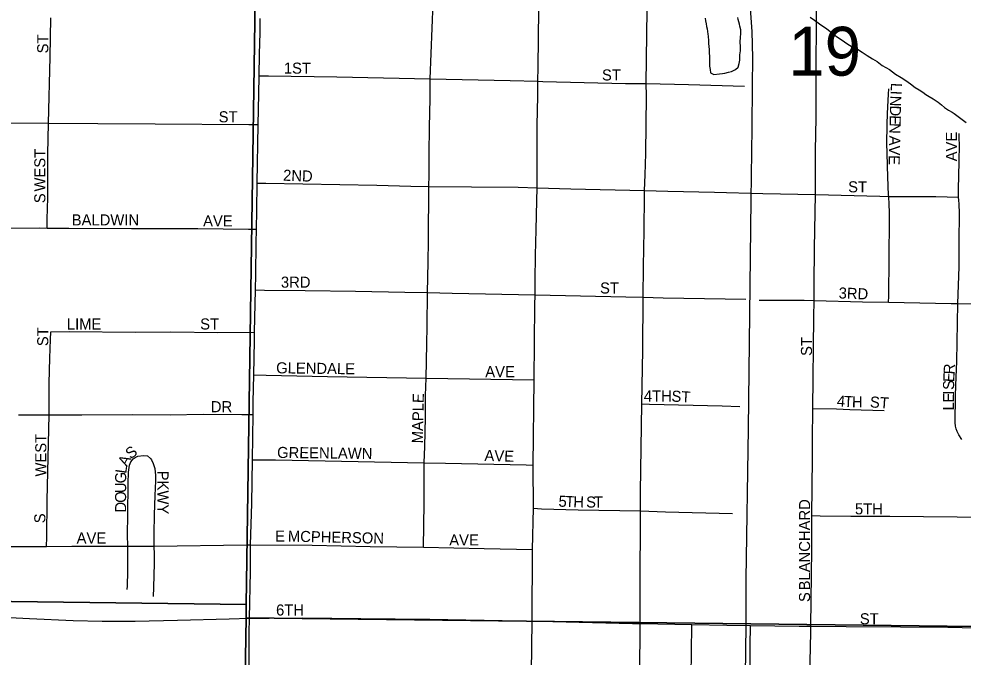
# Model space of a CAD drawing. Extents: x 1587405 to 1714697, y 1028970 to 1155083.
# Drawn here: x 1649935 to 1654205, y 1102813 to 1105700 of the extents above; entities that cross this region are included whole.
import ezdxf

# ---------------------------------------------------------------- set-up
doc = ezdxf.new("R2010")
doc.units = 0
for name, color, linetype in [('GM_X_City_Street', 7, 'Continuous'), ('GM_X_City_Street_Text', 7, 'Continuous'), ('GM_X_Minor_Lake', 7, 'Continuous'), ('GM_X_Minor_River', 7, 'Continuous'), ('GM_X_Rail_Line', 7, 'Continuous'), ('GM_X_Section', 7, 'Continuous'), ('GM_X_Section_Text', 7, 'Continuous')]:
    doc.layers.add(name, color=color, linetype=linetype)

msp = doc.modelspace()

# ---------------------------------------------------------------- linework, layer by layer
at = {"layer": 'GM_X_City_Street'}
for points in [[(1653536.6, 1104905.8), (1653536.7, 1104924.4), (1653537.6, 1105105), (1653539.7, 1105252.3), (1653540.3, 1105465.5), (1653542.3, 1105695.2), (1653545.1, 1105923.6), (1653546.9, 1106033.5), (1653546.5, 1106148.4), (1653547.5, 1106257.9)], [(1651794.9, 1105429.1), (1651808.8, 1105772.9), (1651811.8, 1105871.5), (1651812.3, 1105914.9)], [(1652281.6, 1105417.6), (1652282.3, 1105481.6), (1652286.5, 1105741.4), (1652288, 1105903)], [(1652771.8, 1105407), (1652777.5, 1105852.1), (1652777.5, 1105890.5)], [(1650068.7, 1105227.3), (1650075.5, 1105526.2), (1650078.8, 1105704.7)], [(1651021.5, 1105442.3), (1651023.3, 1105539.8), (1651025.1, 1105637.8), (1651025.5, 1105701.4)], [(1651017.3, 1105222.2), (1651019.9, 1105359.5), (1651021.5, 1105442.3)], [(1651021.5, 1105442.3), (1651063.7, 1105441.7), (1651372.8, 1105437.3), (1651794.9, 1105429.1)], [(1651788.5, 1104941.9), (1651790.4, 1104993), (1651790.3, 1105089.2), (1651791.9, 1105210.5), (1651794.3, 1105340), (1651794.9, 1105429.1)], [(1651794.9, 1105429.1), (1652156.5, 1105420.5), (1652281.6, 1105417.6)], [(1652278.7, 1104935.5), (1652278.9, 1105108.9), (1652277.7, 1105219.2), (1652280.8, 1105350.2), (1652281.6, 1105417.6)], [(1652281.6, 1105417.6), (1652303.9, 1105416.8), (1652678.4, 1105407.7), (1652771.8, 1105407)], [(1652764.3, 1104923.2), (1652766.6, 1104994.1), (1652769.6, 1105090.1), (1652772.6, 1105351.1), (1652771.8, 1105407)], [(1652771.8, 1105407), (1652962.5, 1105402.4), (1653215.7, 1105395.6)], [(1653868.2, 1104896.6), (1653867.8, 1104903.3), (1653866.3, 1104941.3), (1653862.9, 1105034), (1653860.7, 1105095.8), (1653860.1, 1105132.9), (1653861.3, 1105221.6), (1653862.9, 1105271.2), (1653866.1, 1105331.2), (1653867.7, 1105358.6), (1653868.8, 1105383.1)], [(1649688.8, 1105235.7), (1649733.6, 1105231.7), (1649896.9, 1105229.6), (1650068.7, 1105227.3)], [(1650062.2, 1104753.8), (1650062.9, 1104793.7), (1650064.7, 1104890.7), (1650065.6, 1105088.4), (1650068.7, 1105227.3)], [(1650068.7, 1105227.3), (1650291.3, 1105226.3), (1650550.4, 1105224.3), (1650973.8, 1105222.4), (1651017.3, 1105222.2)], [(1651012.2, 1104957), (1651017.3, 1105222.2)], [(1654184.5, 1104893.5), (1654184.6, 1104929.6), (1654186.4, 1105052.5), (1654187.7, 1105131.5), (1654187.3, 1105158.2), (1654186.8, 1105181.8)], [(1651008.8, 1104748.4), (1651009.9, 1104832.4), (1651012.2, 1104957)], [(1651012.2, 1104957), (1651050.9, 1104956.4), (1651552.7, 1104947.3), (1651707.6, 1104943.2), (1651788.5, 1104941.9)], [(1651782.5, 1104462.2), (1651785.2, 1104598.6), (1651786.9, 1104696.2), (1651788.5, 1104941.9)], [(1651788.5, 1104941.9), (1651981.2, 1104939.7), (1652192, 1104937.9), (1652278.7, 1104935.5)], [(1652269, 1104451.8), (1652269.8, 1104516.7), (1652271.1, 1104630.4), (1652274.6, 1104746.2), (1652277.3, 1104876), (1652278.7, 1104935.5)], [(1652278.7, 1104935.5), (1652430.8, 1104931.2), (1652764.3, 1104923.2)], [(1652758.2, 1104440.3), (1652758.9, 1104579.9), (1652762.2, 1104742), (1652763.3, 1104899.6), (1652764.3, 1104923.2)], [(1652764.3, 1104923.2), (1652869.4, 1104920.6), (1653080.9, 1104915.6), (1653298.7, 1104910.5), (1653536.6, 1104905.8)], [(1653531, 1104426.3), (1653531.8, 1104498), (1653532.7, 1104662.1), (1653536.6, 1104905.8)], [(1653536.6, 1104905.8), (1653827.6, 1104897.8), (1653868.2, 1104896.6)], [(1653868.1, 1104418.3), (1653869, 1104445.2), (1653870.4, 1104616.9), (1653872.2, 1104792.9), (1653871.9, 1104826.2), (1653871, 1104859.9), (1653868.2, 1104896.6)], [(1653868.2, 1104896.6), (1654080.9, 1104895.9), (1654184.5, 1104893.5)], [(1654181.5, 1104412.6), (1654186.5, 1104578.7), (1654187, 1104691.9), (1654188.7, 1104820.2), (1654186.8, 1104861.9), (1654185.5, 1104879.3), (1654184.5, 1104893.5)], [(1649680.4, 1104754.7), (1649866.1, 1104753.4), (1650026.6, 1104754), (1650062.2, 1104753.8)], [(1650062.2, 1104753.8), (1650160.4, 1104753.2), (1650443.8, 1104751.9), (1650744.1, 1104750.9), (1650972.6, 1104748.8), (1651008.8, 1104748.4)], [(1651003.9, 1104474.6), (1651005.6, 1104544.2), (1651008, 1104685.8), (1651008.8, 1104748.4)], [(1650999.5, 1104282), (1651003.9, 1104474.6)], [(1651003.9, 1104474.6), (1651045.6, 1104472.9), (1651228.7, 1104471.9), (1651456.8, 1104467.4), (1651679.6, 1104463), (1651782.5, 1104462.2)], [(1651776, 1104074.8), (1651780.1, 1104229.5), (1651781, 1104308.7), (1651782.5, 1104462.2)], [(1651782.5, 1104462.2), (1651894.2, 1104459.6), (1652269, 1104451.8)], [(1652264.9, 1104067.1), (1652268.5, 1104405.2), (1652269, 1104451.8)], [(1652269, 1104451.8), (1652678.7, 1104442.5), (1652758.2, 1104440.3)], [(1652751.6, 1103958.4), (1652756.8, 1104201.8), (1652758.2, 1104440.3)], [(1652758.2, 1104440.3), (1652848.9, 1104438.7), (1653222.4, 1104431.8)], [(1653282.5, 1104427.9), (1653329.8, 1104427), (1653485.4, 1104427.5), (1653531, 1104426.3)], [(1653525.4, 1103937.7), (1653530, 1104350.4), (1653531, 1104426.3)], [(1653531, 1104426.3), (1653750.5, 1104420.3), (1653868.1, 1104418.3)], [(1653868.1, 1104418.3), (1654151.5, 1104412.9), (1654181.5, 1104412.6)], [(1654198.4, 1103797.2), (1654186.1, 1103818.6), (1654178.2, 1103833.1), (1654173.7, 1103845.4), (1654170.9, 1103858.2), (1654169.5, 1103874.6), (1654170.8, 1103993.1), (1654171.9, 1104042.4), (1654176.4, 1104150.6), (1654181.5, 1104412.6)], [(1654181.5, 1104412.6), (1654505.2, 1104410.9)], [(1650070.8, 1103908.4), (1650072.1, 1104051.7), (1650073.9, 1104164.8), (1650077.3, 1104249.5), (1650078.7, 1104283.8)], [(1650078.7, 1104283.8), (1650163.2, 1104285), (1650459.9, 1104283.4), (1650622.4, 1104283.6), (1650833.7, 1104281.8), (1650999.5, 1104282)], [(1650997, 1104089.5), (1650999.7, 1104243.2), (1650999.5, 1104282)], [(1650993.9, 1103910.3), (1650994.7, 1103965.6), (1650997, 1104089.5)], [(1650997, 1104089.5), (1651053, 1104088.2), (1651330.3, 1104081.5), (1651776, 1104074.8)], [(1651768, 1103691.9), (1651769.9, 1103766.1), (1651773.5, 1103896), (1651774.1, 1103996.5), (1651776, 1104074.8)], [(1651776, 1104074.8), (1652264.9, 1104067.1)], [(1652260.6, 1103681.4), (1652264.9, 1104067.1)], [(1652745.4, 1103474.8), (1652746, 1103499.7), (1652745.5, 1103558.4), (1652751.6, 1103958.4)], [(1652751.6, 1103958.4), (1652785.8, 1103957.5), (1653115, 1103949.2), (1653195.7, 1103946.5)], [(1649933.1, 1103908.3), (1650030.9, 1103908.9), (1650070.8, 1103908.4)], [(1650070.8, 1103908.4), (1650219.1, 1103908.5), (1650446.3, 1103910.3), (1650618.7, 1103909.5), (1650767.2, 1103911.3), (1650943.2, 1103910.5), (1650993.9, 1103910.3)], [(1650990.7, 1103705.2), (1650993.9, 1103910.3)], [(1653521.2, 1103453.1), (1653523.7, 1103710.9), (1653523.5, 1103825.8), (1653524.5, 1103907.7), (1653525.4, 1103937.7)], [(1653525.4, 1103937.7), (1653631.8, 1103935.3), (1653692.4, 1103933.3), (1653848.2, 1103928.1)], [(1650060.1, 1103314), (1650060.5, 1103355.6), (1650062.2, 1103520.6), (1650070.8, 1103908.4)], [(1650427.7, 1103315.4), (1650425.9, 1103365.7), (1650427.7, 1103457.2), (1650429.4, 1103597.7), (1650430.5, 1103649.1), (1650435.1, 1103681.4), (1650440.5, 1103696.1), (1650450.7, 1103710), (1650460.2, 1103715.4), (1650472.3, 1103721.9), (1650498.5, 1103725), (1650516.8, 1103722.8), (1650529, 1103711.7), (1650534.4, 1103704.7), (1650542.4, 1103688.7), (1650549.3, 1103665.6), (1650552.8, 1103634.1), (1650552.7, 1103610.2), (1650550, 1103543.6), (1650547, 1103457.2), (1650544.3, 1103371.8), (1650544.8, 1103314.8)], [(1650981.9, 1103321.1), (1650987.3, 1103508), (1650990.7, 1103705.2)], [(1650990.7, 1103705.2), (1651044, 1103705.1), (1651095.2, 1103705), (1651768, 1103691.9)], [(1651763.9, 1103310.4), (1651767.4, 1103508.3), (1651768, 1103691.9)], [(1651768, 1103691.9), (1651863.7, 1103690), (1652228.2, 1103682.4), (1652260.6, 1103681.4)], [(1652261.7, 1103486.5), (1652260.6, 1103681.4)], [(1652257.9, 1103300.4), (1652261.7, 1103486.5)], [(1652261.7, 1103486.5), (1652297.7, 1103482.9), (1652463.4, 1103479.5), (1652745.4, 1103474.8)], [(1652744.4, 1102964.7), (1652744.1, 1103114.4), (1652745.4, 1103474.8)], [(1652745.4, 1103474.8), (1652859.3, 1103470.6), (1653161.5, 1103463.2)], [(1653516.3, 1102952.3), (1653520, 1103300.9), (1653521.2, 1103453.1)], [(1653521.2, 1103453.1), (1653558.7, 1103452.5), (1653697.6, 1103450.3), (1653809, 1103450.2), (1653873.8, 1103449.9), (1654330.6, 1103445.5), (1654390.2, 1103445.7), (1654499.3, 1103444)], [(1649179.4, 1103332.6), (1649186.6, 1103327.6), (1649194.5, 1103322.2), (1649205.9, 1103317.6), (1649222.8, 1103313.4), (1649239.6, 1103312.2), (1649485.8, 1103312.6), (1650060.1, 1103314)], [(1650060.1, 1103314), (1650174.3, 1103314.3), (1650427.7, 1103315.4)], [(1650424.8, 1103119.3), (1650425.2, 1103135.1), (1650427.5, 1103200.3), (1650427.7, 1103315.4)], [(1650427.7, 1103315.4), (1650544.8, 1103314.8)], [(1650544.8, 1103314.8), (1650546.4, 1103276.8), (1650545.7, 1103238.1), (1650543.5, 1103128), (1650541.5, 1103087.2)], [(1650544.8, 1103314.8), (1650965.3, 1103320.3), (1650981.9, 1103321.1)], [(1650977, 1102988.5), (1650981.6, 1103200.4), (1650981.9, 1103321.1)], [(1650981.9, 1103321.1), (1651261.6, 1103319), (1651523, 1103313.6), (1651763.9, 1103310.4)], [(1651763.9, 1103310.4), (1652039.3, 1103304.8), (1652257.9, 1103300.4)], [(1652256, 1102975.8), (1652257.9, 1103300.4)], [(1649622.9, 1103006.1), (1649982.7, 1102987.4), (1650179.9, 1102978.3), (1650311.5, 1102975.4), (1650459.7, 1102975.9), (1650651.4, 1102979.5), (1650885.9, 1102986.6), (1650977, 1102988.5)], [(1650975, 1102654), (1650976.1, 1102761.1), (1650975.8, 1102906.9), (1650975.7, 1102923.1), (1650977, 1102988.5)], [(1650977, 1102988.5), (1651022.6, 1102988.8), (1651066.9, 1102989.2)], [(1651066.9, 1102989.2), (1651219.2, 1102990.2), (1651481.5, 1102988.2), (1651792.9, 1102984.6), (1652119.8, 1102978.3), (1652256, 1102975.8)], [(1652249.9, 1102520.5), (1652250.6, 1102569.9), (1652252.3, 1102742.9), (1652256, 1102975.8)], [(1652256, 1102975.8), (1652289.4, 1102975), (1652529.3, 1102969.2), (1652709.7, 1102965.4), (1652744.4, 1102964.7)], [(1652723.8, 1101578), (1652727, 1101816.8), (1652731.5, 1102104.2), (1652734.1, 1102392.4), (1652736.8, 1102572.2), (1652742.6, 1102772.1), (1652744.3, 1102925), (1652744.4, 1102964.7)], [(1652744.4, 1102964.7), (1652824.3, 1102963.1), (1652977.3, 1102960.5)], [(1652961.1, 1101574), (1652961, 1101606.1), (1652962.7, 1101655.2), (1652962.6, 1101784.9), (1652964.1, 1101833.5), (1652966.2, 1102013.2), (1652968.2, 1102062.3), (1652967.7, 1102111.4), (1652967.5, 1102176.9), (1652968.1, 1102291.5), (1652968.2, 1102389.7), (1652974.6, 1102700.7), (1652977.1, 1102864.3), (1652977.2, 1102929.8), (1652977.3, 1102960.5)], [(1652977.3, 1102960.5), (1653135.8, 1102957.8), (1653243.8, 1102956.1)], [(1653228.9, 1101568.7), (1653231, 1101609.1), (1653231.5, 1101658.6), (1653228.6, 1101822.8), (1653230.7, 1102114.3), (1653235.1, 1102277.9), (1653241.7, 1102802.7), (1653242.1, 1102901.3), (1653242.6, 1102917.7), (1653243.8, 1102956.1)], [(1653243.8, 1102956.1), (1653463.4, 1102952.6), (1653516.3, 1102952.3)], [(1653505.6, 1101564.3), (1653507, 1101660.2), (1653506.8, 1101758.8), (1653508.9, 1102119.7), (1653512.7, 1102447.8), (1653512.2, 1102530), (1653513.5, 1102792.5), (1653515.9, 1102923.6), (1653516.3, 1102952.3)], [(1653516.3, 1102952.3), (1653676.5, 1102951.3), (1653922.3, 1102949.4), (1654135.5, 1102948.2), (1654332.1, 1102944.6), (1654412.6, 1102944.6), (1654493.3, 1102943.2)]]:
    msp.add_lwpolyline(points, dxfattribs=at)
at = {"layer": 'GM_X_Minor_Lake'}
msp.add_lwpolyline([(1653037.8, 1105703.5), (1653039.5, 1105691.4), (1653043.3, 1105677.3), (1653045, 1105665.2), (1653046.8, 1105655.1), (1653048.6, 1105643.1), (1653050.4, 1105631), (1653052.2, 1105620.9), (1653053.8, 1105600.8), (1653053.5, 1105588.8), (1653055.2, 1105574.7), (1653057, 1105560.6), (1653056.6, 1105544.6), (1653058.3, 1105530.5), (1653058.1, 1105518.5), (1653057.9, 1105506.5), (1653057.7, 1105496.4), (1653057.5, 1105486.4), (1653061.1, 1105470.3), (1653062.9, 1105456.2), (1653076.7, 1105447.9), (1653102.9, 1105451.4), (1653117, 1105453.1), (1653127, 1105454.9), (1653143.2, 1105458.6), (1653157.3, 1105462.3), (1653175.5, 1105470), (1653187.8, 1105481.8), (1653192.1, 1105497.7), (1653194.5, 1105513.7), (1653194.7, 1105523.8), (1653195, 1105537.8), (1653197.3, 1105555.8), (1653197.7, 1105573.9), (1653196.1, 1105596), (1653198.5, 1105616), (1653198.9, 1105634), (1653199.2, 1105650.1), (1653195.6, 1105666.2), (1653193.7, 1105676.2), (1653189.9, 1105686.4), (1653188.1, 1105696.4), (1653186.3, 1105706.5)], dxfattribs=at)
at = {"layer": 'GM_X_Minor_River'}
for points in [[(1653513.4, 1105707.9), (1653533.2, 1105693.5), (1653555, 1105677), (1653588.6, 1105654.2), (1653610.3, 1105637.8), (1653632, 1105619.3), (1653657.8, 1105602.7), (1653679.6, 1105588.2)], [(1653679.6, 1105588.2), (1653703.4, 1105573.7), (1653727.2, 1105563.2), (1653749, 1105548.7), (1653770.8, 1105534.2), (1653794.6, 1105519.7), (1653816.4, 1105507.2), (1653838.1, 1105488.7), (1653871.8, 1105470), (1653899.5, 1105449.4), (1653925.3, 1105434.8), (1653945.1, 1105420.4), (1653966.8, 1105405.9), (1653988.6, 1105389.4), (1654006.4, 1105379), (1654022.3, 1105368.7), (1654036.1, 1105358.4), (1654052, 1105348), (1654069.8, 1105337.6), (1654091.6, 1105323.1), (1654107.4, 1105310.8), (1654121.2, 1105298.5), (1654139, 1105286.1), (1654154.9, 1105277.7), (1654164.8, 1105271.5), (1654218.1, 1105230.3)]]:
    msp.add_lwpolyline(points, dxfattribs=at)
at = {"layer": 'GM_X_Rail_Line'}
for points in [[(1653224, 1102956.5), (1653224, 1103165.4), (1653234.1, 1103846.6), (1653246.7, 1104880.7), (1653251, 1105207.4), (1653252.6, 1105396.8), (1653253.5, 1105524), (1653251, 1105641.9), (1653242.5, 1105747.1)], [(1653459.9, 1097628.5), (1653478.1, 1097848.8), (1653484.1, 1097957.6), (1653490.8, 1098497.6), (1653491.5, 1098762.2), (1653486.8, 1098940.2), (1653479.4, 1099030.9), (1653468, 1099113.5), (1653452.5, 1099196.8), (1653429.7, 1099288.8), (1653340.4, 1099585.7), (1653294, 1099745.5), (1653252.4, 1099900.7), (1653226.9, 1100019.6), (1653210.7, 1100123.7), (1653201.3, 1100190.2), (1653195.3, 1100282.2), (1653190.6, 1100513.2), (1653200.1, 1101150), (1653224, 1102956.5)]]:
    msp.add_lwpolyline(points, dxfattribs=at)
at = {"layer": 'GM_X_Section'}
for points in [[(1645734.9, 1108387.2), (1651041.3, 1108325.5), (1650961.9, 1103051.3), (1645653.7, 1103119)], [(1651041.3, 1108325.5), (1656163.1, 1108222.1), (1656161.5, 1102928.9), (1650963.1, 1102991.2), (1650961.9, 1103051.3)], [(1650961.9, 1103051.3), (1650963.1, 1102991.2), (1650873.6, 1097703.2), (1645545.8, 1097805.3), (1645653.7, 1103119)], [(1656161.5, 1102928.9), (1656123.9, 1097642.2), (1650873.6, 1097703.2), (1650963.1, 1102991.2)]]:
    msp.add_lwpolyline(points, close=True, dxfattribs=at)

# ---------------------------------------------------------------- texts
at = {"layer": 'GM_X_City_Street_Text'}
for s, rotation, p in [('ST', 90, (1650067.4, 1105543.7)), ('1ST', 0, (1651132.8, 1105451.9)), ('ST', 0, (1652571.6, 1105421.1)), ('L', 266.8838, (1653879, 1105411.1)), ('I', 266.8517, (1653877.1, 1105376)), ('N', 268.045, (1653875.8, 1105352.9)), ('ST', 0, (1650838, 1105231.9)), ('D', 268.8218, (1653874.3, 1105308.2)), ('E', 268.5795, (1653873.4, 1105264.3)), ('N', 268.5966, (1653872.5, 1105229)), ('A', 268.5853, (1653871.1, 1105171.8)), ('AVE', 90, (1654177, 1105055.3)), ('WEST', 90, (1650054.2, 1104918.9)), ('V', 268.5966, (1653870, 1105127.8)), ('E', 268.5795, (1653868.9, 1105083.9)), ('2ND', 357.8801, (1651128.7, 1104967.9)), ('ST', 0, (1653684.8, 1104915.1)), ('S', 90, (1650054.2, 1104866.1)), ('BALDWIN', 0, (1650173.6, 1104765.5)), ('AVE', 0, (1650767.6, 1104761.1)), ('3RD', 0, (1651119.6, 1104483.9)), ('ST', 0, (1652562.8, 1104457.5)), ('3RD', 357.7987, (1653641.1, 1104435.5)), ('LIME', 0, (1650151.6, 1104294.7)), ('ST', 0, (1650754.4, 1104294.7)), ('ST', 90, (1650067.4, 1104219.3)), ('ST', 90, (1653521.4, 1104175.3)), ('GLENDALE', 359.2262, (1651097.7, 1104096.7)), ('AVE', 0, (1652043.6, 1104079.1)), ('R', 87.4007, (1654165.9, 1104091.1)), ('E', 87.622, (1654164.5, 1104055.9)), ('S', 88.9618, (1654163.8, 1104021.1)), ('MAPLE', 88.7817, (1651761.4, 1103779.5)), ('4TH', 0, (1652760.8, 1103969.1)), ('ST', 356.4118, (1652884.6, 1103969.1)), ('4', 356.0323, (1653632.7, 1103947.1)), ('T', 357.0939, (1653664.4, 1103944.9)), ('I', 89.9573, (1654163.8, 1103999.3)), ('E', 89.9453, (1654163.8, 1103964.1)), ('DR', 0, (1650802.8, 1103920.7)), ('H', 359.5719, (1653701.9, 1103943)), ('ST', 356.1879, (1653782.2, 1103942.7)), ('L', 89.9727, (1654163.8, 1103928.9)), ('WEST', 90, (1650058.6, 1103629.7)), ('S', 37.2087, (1650439.8, 1103706.3)), ('GREENLAWN', 359.3493, (1651102.1, 1103713.9)), ('AVE', 358.0261, (1652039.5, 1103700.7)), ('A', 62.8583, (1650423.5, 1103671.7)), ('L', 81.584, (1650419.6, 1103640.9)), ('G', 89.847, (1650419.7, 1103598.8)), ('PKWY', 270, (1650561.4, 1103656.1)), ('U', 89.8578, (1650419.6, 1103554.9)), ('O', 89.847, (1650419.5, 1103510.8)), ('5', 357.189, (1652374.1, 1103493.9)), ('T', 357.1853, (1652404.8, 1103492.4)), ('H', 358.6528, (1652441.4, 1103490.6)), ('S', 359.9707, (1652499.8, 1103489.5)), ('T', 359.9956, (1652535, 1103489.5)), ('D', 89.8688, (1650419.4, 1103466.9)), ('BLANCHARD', 90, (1653512.6, 1103114.9)), ('5TH', 0, (1653715.6, 1103458.7)), ('S', 90, (1650054.2, 1103418.5)), ('AVE', 0, (1650195.6, 1103326.7)), ('E', 0, (1651093.2, 1103335.5)), ('MCPHERSON', 358.6528, (1651150.6, 1103335.5)), ('AVE', 0, (1651880.8, 1103317.9)), ('S', 90, (1653512.6, 1103062.1)), ('6TH', 0, (1651097.6, 1103001.1)), ('ST', 0, (1653737.6, 1102961.5))]:
    msp.add_text(s, height=50, rotation=rotation, dxfattribs=at).set_placement(p)
at = {"layer": 'GM_X_Section_Text'}
msp.add_text('19', height=221, rotation=0, dxfattribs=at).set_placement((1653414.2, 1105442.8))

doc.saveas('drawing.dxf')
